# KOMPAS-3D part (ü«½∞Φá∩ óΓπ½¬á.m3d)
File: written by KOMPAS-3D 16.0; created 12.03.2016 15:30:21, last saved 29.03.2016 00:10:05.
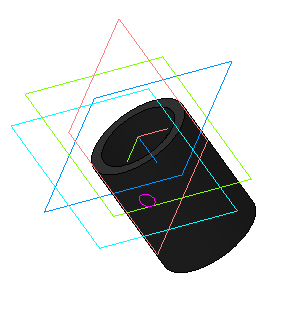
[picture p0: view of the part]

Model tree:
1. Эскиз:1
2. Операция выдавливания:1
     Расстояние 1 = 40
3. Смещенная плоскость:1
     Расстояние = 14
4. Эскиз:2
5. Вырезать элемент выдавливания:2
     Расстояние 1 = 30
6. Неуказанная шероховатость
